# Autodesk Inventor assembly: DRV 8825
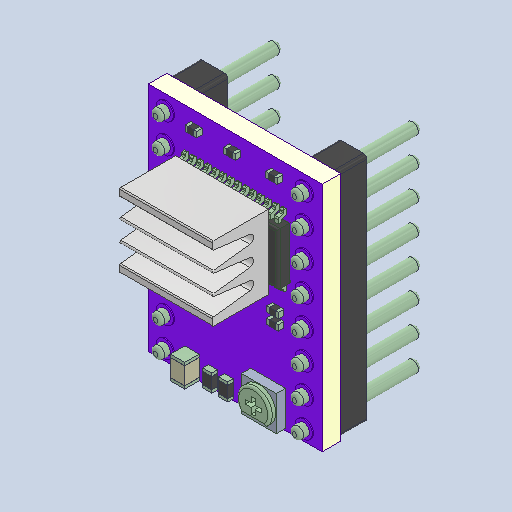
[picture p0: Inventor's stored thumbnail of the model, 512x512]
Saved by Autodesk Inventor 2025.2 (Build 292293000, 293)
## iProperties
Created: 2025-04
Part Number: DRV 8825
Description: PART--DESC
Document SubType Name: Assembly
Designer: BennF
Author: BennF
Revision Number: NONE
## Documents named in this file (9)
- C:\Users\BennF\Nextcloud\Benutzer\CNC JarBeRi\existing parts\Electronics\RepRap A4988 Shied (USE WITHOUT ARDUINO)\reprap-a4988-1.snapshot.1\RepRap\RepRap\DRV 8825_3.iam
- C:\Users\BennF\Nextcloud\Benutzer\CNC JarBeRi\existing parts\Electronics\RepRap A4988 Shied (USE WITHOUT ARDUINO)\reprap-a4988-1.snapshot.1\RepRap\RepRap\DRV 8825 Geometry.ipt
- C:\Users\BennF\Nextcloud\Benutzer\CNC JarBeRi\existing parts\Electronics\RepRap A4988 Shied (USE WITHOUT ARDUINO)\reprap-a4988-1.snapshot.1\RepRap\RepRap\PCB.ipt
- C:\Users\BennF\Nextcloud\Benutzer\CNC JarBeRi\existing parts\Electronics\RepRap A4988 Shied (USE WITHOUT ARDUINO)\reprap-a4988-1.snapshot.1\RepRap\RepRap\SMD Pot.ipt
- C:\Users\BennF\Nextcloud\Benutzer\CNC JarBeRi\existing parts\Electronics\RepRap A4988 Shied (USE WITHOUT ARDUINO)\reprap-a4988-1.snapshot.1\RepRap\RepRap\0603 Resistor.ipt
- C:\Users\BennF\Nextcloud\Benutzer\CNC JarBeRi\existing parts\Electronics\RepRap A4988 Shied (USE WITHOUT ARDUINO)\reprap-a4988-1.snapshot.1\RepRap\RepRap\0805 Capacitor.ipt
- C:\Users\BennF\Nextcloud\Benutzer\CNC JarBeRi\existing parts\Electronics\RepRap A4988 Shied (USE WITHOUT ARDUINO)\reprap-a4988-1.snapshot.1\RepRap\RepRap\0402 Resistor.ipt
- C:\Users\BennF\Nextcloud\Benutzer\CNC JarBeRi\existing parts\Electronics\RepRap A4988 Shied (USE WITHOUT ARDUINO)\reprap-a4988-1.snapshot.1\RepRap\RepRap\DRV8825 IC.ipt
- C:\Users\BennF\Nextcloud\Benutzer\CNC JarBeRi\existing parts\Electronics\RepRap A4988 Shied (USE WITHOUT ARDUINO)\reprap-a4988-1.snapshot.1\RepRap\RepRap\8 pin Header.ipt
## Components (16 placed, 8 different names)
1. DRV 8825 Geometry
2. PCB
3. SMD Pot
4. 0603 Resistor
5. 0603 Resistor:1
6. 0805 Capacitor
7. 0402 Resistor
8. 0402 Resistor:1
9. 0402 Resistor:2
10. 0402 Resistor:3
11. 0402 Resistor:4
12. 0402 Resistor:5
13. 0402 Resistor:6
14. DRV8825 IC
15. 8 pin Header
16. 8 pin Header:1
